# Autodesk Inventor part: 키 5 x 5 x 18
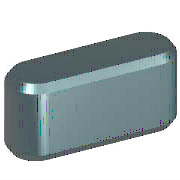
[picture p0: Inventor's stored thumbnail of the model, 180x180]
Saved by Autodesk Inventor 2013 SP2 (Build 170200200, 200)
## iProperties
Created: 2012-02
Part Number: 키 5 x 5 x 18
Material: 강철, 연강
Description: 키 및 해당 키홈
Document SubType Name: Modeling
Standard: KS B 1311
Designer: mduedu
Standards Organization: KS
Language: ko-KR
Size Designation: 5 x 5 x 18
Categories: <MemberInstance><Categories><Category DisplayName="샤프트 부품" InternalName="7f7aeb1f-a693-4053-b835-cee3144e0d98" Mnemonic="SHFT"><Category DisplayName="키" Interna
Density: 1 g/cm^3
IsCustomPart: 1
Author: mduedu
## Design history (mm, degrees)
workplane "Work Plane1"
workplane "Work Plane2"
sketch "스케치1"
  geometry: L1 (2.5, 2.5)-(23.5, 2.5); L2 (23.5, -2.5)-(2.5, -2.5); L3 (0, 8.9)-(0, -4.4) reference; L4 (-5.6, 0)-(33.6, 0) reference; L5 (26, 0)-(26, 7); A1 r 2.5 centre (2.5, 0) between (2.5, 2.5) and (2.5, -2.5); A2 r 2.5 centre (23.5, 0) between (23.5, -2.5) and (23.5, 2.5)
  constraints: 6 end point, 5 point on circle, 4 tangent, 3 point on line, 2 centre point, 1 horizontal, 1 parallel, 1 perpendicular
  dimensions: "d0" = 2.5 radius of A1 (= 0.5 x PB); "d13" = 2.5 radius of A2 (= 0.5 x PB); "d14" = 26 distance between parallel lines of L5 L3 (= NLG)
extrude "본체1" new body sketch "스케치1" taper "d3" = 0 deg; stored distance "d4" = 10
workplane "Work Plane3"
body "Solid1"
chamfer "모따기1" distance "d8" = 0.4 (= PHH); stored, may be unused: second distance "d9" = 0.4 (= PHH), angle "d15" = 45 deg
other parameters: "d1" = -3 (= -PNT), "d2" = 2 (= PH - PNT), "NLG" = 26 [user parameter; used in 3 equation terms], "PB" = 5 [user parameter; used in 2 equation terms], "PNT" = 3 [user parameter; used in 2 equation terms], "PH" = 5 [user parameter; used in 1 equation term], "PHH" = 0.4 [user parameter; used in 2 equation terms], "d10" = 0, "d16" = 0, "d17" = 0, "d18" = 0, "WDMIN" = 12 [user parameter], "PLB2" = 26 (= NLG) [user parameter], "WDMAX" = 17 [user parameter], "PLB1" = 26 (= NLG) [user parameter], "RR" = 0.16 [user parameter], "PUEB" = 2.3 [user parameter]
